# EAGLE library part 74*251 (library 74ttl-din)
1 of 8 data SELECTOR/MULTIPLEXER, 3-state
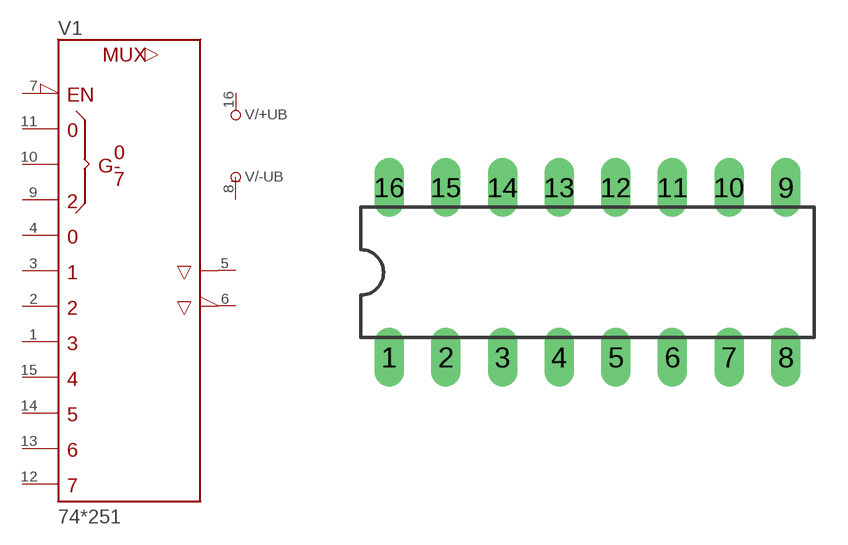
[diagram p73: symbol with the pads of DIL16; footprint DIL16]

Designator prefix V; gates /+UB=+UB /-UB=-UB 1=251

## 74251N  [DIL16]
1  1:D3  in
2  1:D2  in
3  1:D1  in
4  1:D0  in
5  1:Y  hiz
6  1:W  hiz
7  1:G\  in
8  /-UB:-UB  pwr
9  1:C  in
10  1:B  in
11  1:A  in
12  1:D7  in
13  1:D6  in
14  1:D5  in
15  1:D4  in
16  /+UB:+UB  pwr

## Footprint DIL16 (pad centres in mm)
Dual In Line Package
drill 0.813 long: 1 -8.89,-3.81; 2 -6.35,-3.81; 3 -3.81,-3.81; 4 -1.27,-3.81; 5 1.27,-3.81; 6 3.81,-3.81; 7 6.35,-3.81; 8 8.89,-3.81; 9 8.89,3.81; 10 6.35,3.81; 11 3.81,3.81; 12 1.27,3.81; 13 -1.27,3.81; 14 -3.81,3.81; 15 -6.35,3.81; 16 -8.89,3.81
